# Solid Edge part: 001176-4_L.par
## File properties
Last saved by: morva
Revision: 82
Accuracy: 0.990
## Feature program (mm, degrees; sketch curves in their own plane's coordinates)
body "unnamed Body 1"
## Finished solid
Body 1: solid body, 14 faces, 28 edges, 18 vertices.
  Faces by surface: cylinder 6, plane 4, torus 4
  Edges by curve: circle 19, line 6, spline 3
Bounding box of the edges (mm; curved faces can reach further): 8.285 x 11.756 x 6.068, from (535.2966, 405.3463, -81.308) to (543.5819, 417.1023, -75.24).
Cylindrical faces by radius (mm): R0.75 x2, R1.5 x2, R2.5 x2
Toroidal faces (ring radius, tube radius in mm): R1.125 r0.375 x2, R1.125 r1.5156 x2
Planar faces by outward normal: oblique 4
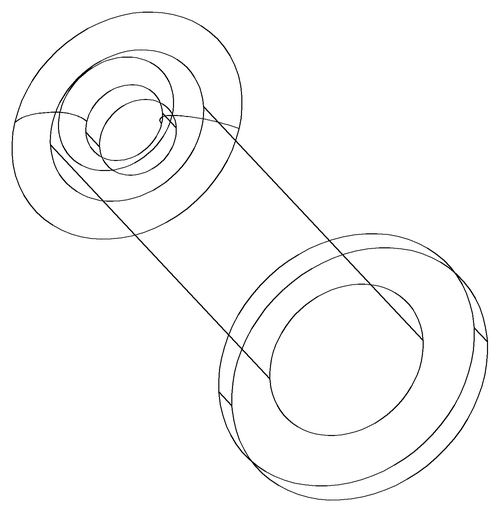
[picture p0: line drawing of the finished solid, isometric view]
